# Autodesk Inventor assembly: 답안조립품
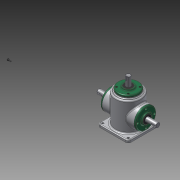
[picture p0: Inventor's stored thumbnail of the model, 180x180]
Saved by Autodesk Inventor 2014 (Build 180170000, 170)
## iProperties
Created: 2015-10
Part Number: 답안조립품
Document SubType Name: Assembly
Designer: user
Author: user
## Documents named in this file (14)
- C:\Users\user\Desktop\451008v1006\답안조립품.iam
- C:\Users\user\Desktop\451008v1006\M4.ipt
- C:\Users\user\Desktop\451008v1006\메인 베벨기어.ipt
- C:\Users\user\Desktop\451008v1006\메인 축.ipt
- 메인 축.ipt
- C:\Users\user\Desktop\451008v1006\베어링 6203.ipt
- C:\Users\user\Desktop\451008v1006\본체.ipt
- C:\Users\user\Desktop\451008v1006\서브 베벨기어.ipt
- C:\Users\user\Desktop\451008v1006\서브 축.ipt
- 서브 축.ipt
- C:\Users\user\Desktop\451008v1006\오일실.ipt
- C:\Users\user\Desktop\451008v1006\커버.ipt
- C:\Users\user\Desktop\451008v1006\키 4x4.ipt
- C:\Users\user\Desktop\451008v1006\키 5x5.ipt
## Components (1 placed, 1 different names)
1. M4:1
## Named parameters: d14_d12 = 0, d15_d13 = 0, d16_d6 = 0, d17_d7 = 180 deg
